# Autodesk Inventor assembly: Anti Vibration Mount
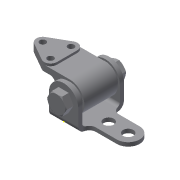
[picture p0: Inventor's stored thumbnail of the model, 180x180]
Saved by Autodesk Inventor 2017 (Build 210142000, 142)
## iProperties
Created: 2011-07
Part Number: Anti Vibration Mount
Document SubType Name: Assembly
Designer: CadCim
Author: CadCim
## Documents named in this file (5)
- D:\New folder\New folder (3)\Inventor_2016_tut\c09_Inv_tut_2016\c09_tut03_inv\Anti Vibration Mount\Anti Vibration Mount.iam
- D:\New folder\New folder (3)\Inventor_2016_tut\c09_Inv_tut_2016\c09_tut03_inv\Anti Vibration Mount\Yoke Plate.ipt
- D:\New folder\New folder (3)\Inventor_2016_tut\c09_Inv_tut_2016\c09_tut03_inv\Anti Vibration Mount\Body-Bushing Ruber.iam
- D:\New folder\New folder (3)\Inventor_2016_tut\c09_Inv_tut_2016\c09_tut03_inv\Anti Vibration Mount\Hex Bolt.ipt
- D:\New folder\New folder (3)\Inventor_2016_tut\c09_Inv_tut_2016\c09_tut03_inv\Anti Vibration Mount\Nut.ipt
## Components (4 placed, 4 different names)
1. Yoke Plate:1 — Insert:1, Angle:1, Mate:1, Mate:2, Mate:3
2. Body-Bushing Ruber:1 [sub-assembly] — Insert:1, Angle:1
3. Hex Bolt:1 — Mate:2, Mate:3, Mate:4
4. Nut:1 — Mate:1, Mate:4
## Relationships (6: Mate 4, Insert 1, Angle 1)
- Insert:1: Yoke Plate:1 ↔ Body-Bushing Ruber:1
- Angle:1: Yoke Plate:1 ↔ Body-Bushing Ruber:1
- Mate:1: Yoke Plate:1 ↔ Nut:1
- Mate:2: Yoke Plate:1 ↔ Hex Bolt:1
- Mate:3: Yoke Plate:1 ↔ Hex Bolt:1
- Mate:4: Hex Bolt:1 ↔ Nut:1
